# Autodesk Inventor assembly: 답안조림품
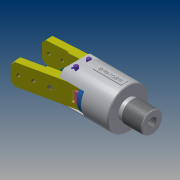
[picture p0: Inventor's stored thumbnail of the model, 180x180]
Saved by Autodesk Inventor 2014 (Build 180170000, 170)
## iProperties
Created: 2019-02
Part Number: 답안조림품
Document SubType Name: Assembly
Designer: 603-18
Author: 603-18
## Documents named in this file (11)
- C:\Users\603-18\Desktop\490208V1002\답안조림품.iam
- C:\Users\603-18\Desktop\490208V1002\본체.ipt
- C:\Users\603-18\Desktop\490208V1002\E-링.ipt
- C:\Users\603-18\Desktop\490208V1002\O-링.ipt
- C:\Users\603-18\Desktop\490208V1002\가이드핀.ipt
- C:\Users\603-18\Desktop\490208V1002\부시.ipt
- C:\Users\603-18\Desktop\490208V1002\스프링.ipt
- C:\Users\603-18\Desktop\490208V1002\평행핀 6x28.ipt
- C:\Users\603-18\Desktop\490208V1002\피스톤.ipt
- C:\Users\603-18\Desktop\490208V1002\핀.ipt
- C:\Users\603-18\Desktop\490208V1002\핑거.ipt
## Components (12 placed, 6 different names)
1. E-링:1 — 각도:2
2. O-링:1
3. 가이드핀:1
4. 피스톤:1 — 각도:5
5. 핀:1
6. 핑거:1 — 각도:3
7. 핑거:2 — 각도:4
8. 가이드핀:2
9. 핀:2 — 각도:1, 각도:2
10. E-링:2 — 각도:1
11. E-링:3
12. E-링:5
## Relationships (5: Angle 5)
- 각도:1 [Angle]: 핀:2 ↔ E-링:2
- 각도:2 [Angle]: E-링:1 ↔ 핀:2
- 각도:3 [Angle]: 핑거:1
- 각도:4 [Angle]: 핑거:2
- 각도:5 [Angle]: 피스톤:1
